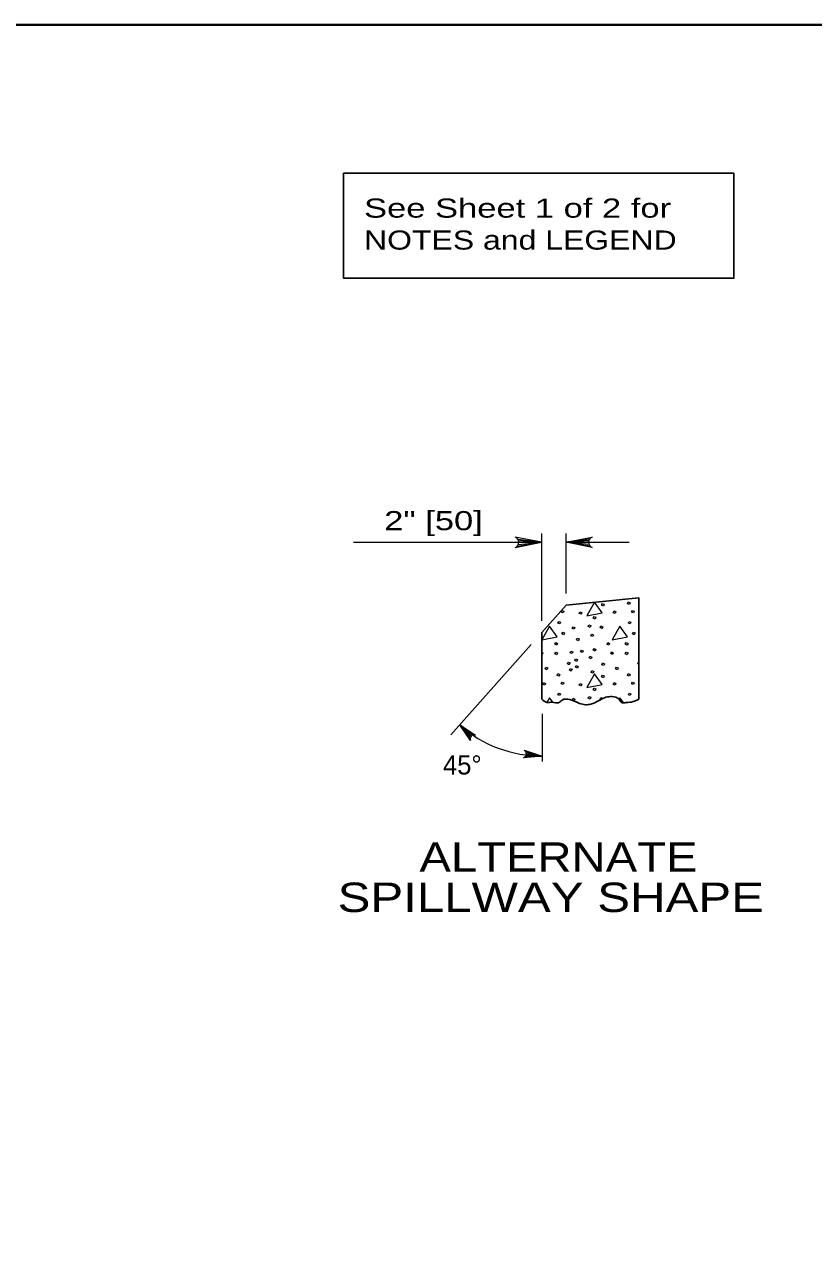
# Model space of a CAD drawing. Extents: x 1083.1 to 1123, y 697.4 to 741.4.
# Drawn here: x 1095.55 to 1101.99, y 708.76 to 718.85 of the extents above; entities that cross this region are included whole.
import ezdxf
from ezdxf.enums import TextEntityAlignment as Align

# ---------------------------------------------------------------- set-up
doc = ezdxf.new("R2010")
doc.units = 0
doc.header["$LTSCALE"] = 0.062
doc.layers.add('1', color=7, linetype='Continuous', lineweight=13)

msp = doc.modelspace()

# ---------------------------------------------------------------- linework, layer by layer
at = {"layer": '1', "lineweight": 25}
for p, q in [((1085.12642, 718.85408), (1116.62642, 718.85408)), ((1099.77208, 713.898), (1099.97033, 714.12092)), ((1099.77208, 713.35442), (1099.77208, 713.898))]:
    msp.add_line(p, q, dxfattribs=at)
at = {"layer": '1'}
for p, q in [((1099.77208, 713.9925), (1099.77208, 714.7035)), ((1099.97033, 714.21542), (1099.97033, 714.7035)), ((1098.23525, 714.63275), (1099.77067, 714.63275)), ((1099.5745, 714.60275), (1099.77067, 714.63275)), ((1099.57675, 714.65983), (1099.77067, 714.63275)), ((1099.58192, 714.61533), (1099.77067, 714.63275)), ((1099.58333, 714.64642), (1099.77067, 714.63275)), ((1099.58533, 714.63275), (1099.77067, 714.63275)), ((1100.16283, 714.65983), (1099.96892, 714.63275)), ((1100.15625, 714.64642), (1099.96892, 714.63275)), ((1100.15775, 714.63275), (1099.96892, 714.63275)), ((1099.96892, 714.63275), (1100.48658, 714.63275)), ((1100.15425, 714.63275), (1099.96892, 714.63275)), ((1100.15767, 714.61533), (1099.96892, 714.63275)), ((1100.16508, 714.60275), (1099.96892, 714.63275)), ((1099.03, 713.0635), (1099.6855, 713.80058)), ((1100.56267, 713.65458), (1100.56425, 713.654)), ((1099.836, 713.36533), (1099.81442, 713.32675)), ((1099.862, 713.32825), (1099.836, 713.36533)), ((1100.41042, 713.36533), (1100.4025, 713.35108)), ((1100.43825, 713.32567), (1100.41042, 713.36533)), ((1099.77675, 713.23475), (1099.77675, 712.84425)), ((1099.19658, 713.05267), (1099.10275, 713.14333)), ((1099.19017, 713.04217), (1099.10275, 713.14333)), ((1099.188, 713.0325), (1099.10275, 713.14333)), ((1099.20467, 713.05867), (1099.10275, 713.14333)), ((1099.2145, 713.06267), (1099.10275, 713.14333)), ((1099.63833, 712.88575), (1099.77658, 712.88933)), ((1099.64142, 712.92575), (1099.77658, 712.88933)), ((1099.644, 712.89467), (1099.77658, 712.88933)), ((1099.64525, 712.91683), (1099.77658, 712.88933)), ((1099.64633, 712.90383), (1099.77658, 712.88933))]:
    msp.add_line(p, q, dxfattribs=at)
at = {"layer": '1', "lineweight": 40}
msp.add_lwpolyline([(1085.12642, 718.85408), (1116.62642, 718.85408), (1116.62642, 697.85408), (1085.12642, 697.85408)], close=True, dxfattribs=at)
at = {"layer": '1', "lineweight": 25}
msp.add_lwpolyline([(1098.15567, 717.64242), (1101.33942, 717.64242), (1101.33942, 716.786), (1098.15567, 716.786)], close=True, dxfattribs=at)
at = {"layer": '1'}
for points in [[(1099.5565, 714.58992), (1099.77067, 714.63275), (1099.5565, 714.67558)], [(1100.18308, 714.58992), (1099.96892, 714.63275), (1100.18308, 714.67558)], [(1100.20183, 714.14342), (1100.14033, 714.0335), (1100.26433, 714.05767), (1100.20392, 714.14375)], [(1099.77208, 713.73667), (1099.7815, 713.73217), (1099.7755, 713.71808), (1099.77208, 713.71967)], [(1100.56425, 713.6375), (1100.55658, 713.6405), (1100.56267, 713.65458)], [(1100.2545, 713.34975), (1100.24817, 713.35225), (1100.25425, 713.36742)], [(1100.25425, 713.36742), (1100.26933, 713.36033), (1100.26733, 713.35567)], [(1099.19042, 713.01708), (1099.10275, 713.14333), (1099.23275, 713.06058)], [(1099.62958, 712.93633), (1099.77658, 712.88933), (1099.62283, 712.87617)]]:
    msp.add_lwpolyline(points, dxfattribs=at)
at = {"layer": '1', "lineweight": 25}
msp.add_lwpolyline([(1099.97033, 714.12092), (1100.56425, 714.17892), (1100.56425, 713.35442)], dxfattribs=at)
at = {"layer": '1'}
for points in [[(1100.26733, 714.13425), (1100.28242, 714.12725), (1100.27542, 714.11317), (1100.26025, 714.11917)], [(1100.478, 714.14642), (1100.49308, 714.14033), (1100.48708, 714.12625), (1100.47192, 714.13225)], [(1099.91058, 713.98717), (1099.92567, 713.98108), (1099.91958, 713.967), (1099.9045, 713.97308)], [(1099.93775, 714.07683), (1099.95292, 714.07083), (1099.94583, 714.05667), (1099.93075, 714.06275)], [(1100.08392, 714.06675), (1100.099, 714.06075), (1100.092, 714.04658), (1100.07683, 714.05267)], [(1100.19883, 714.0275), (1100.21392, 714.02142), (1100.20783, 714.00633), (1100.19275, 714.01333)], [(1100.36208, 714.07283), (1100.37717, 714.06675), (1100.37117, 714.05267), (1100.356, 714.05867)], [(1100.485, 713.98717), (1100.50017, 713.98108), (1100.49408, 713.967), (1100.479, 713.97308)], [(1100.51225, 714.07683), (1100.52733, 714.07083), (1100.52033, 714.05667), (1100.50517, 714.06275)], [(1099.836, 713.94983), (1099.7735, 713.838), (1099.89742, 713.86217)], [(1099.94383, 713.9005), (1099.95892, 713.89342), (1099.95183, 713.87933), (1099.93675, 713.88533)], [(1100.0275, 713.94483), (1100.04258, 713.93775), (1100.0365, 713.92367), (1100.02142, 713.93075)], [(1100.1575, 713.95992), (1100.17258, 713.95392), (1100.16658, 713.93875), (1100.15142, 713.94583)], [(1100.18067, 713.88433), (1100.19575, 713.87833), (1100.18875, 713.86425), (1100.17358, 713.87025)], [(1100.25425, 713.95192), (1100.26933, 713.94483), (1100.26333, 713.93075), (1100.24817, 713.93675)], [(1100.41042, 713.94983), (1100.34792, 713.838), (1100.47192, 713.86217)], [(1100.51825, 713.9005), (1100.53342, 713.89342), (1100.52633, 713.87933), (1100.51125, 713.88533)], [(1099.88633, 713.81483), (1099.9015, 713.80875), (1099.89442, 713.79467), (1099.87933, 713.80075)], [(1100.06175, 713.85108), (1100.07683, 713.84508), (1100.07083, 713.82992), (1100.05567, 713.837)], [(1100.31067, 713.81483), (1100.32575, 713.80775), (1100.31975, 713.79367), (1100.30458, 713.79975)], [(1100.46083, 713.81483), (1100.47592, 713.80875), (1100.46892, 713.79467), (1100.45375, 713.80075)], [(1099.88633, 713.73625), (1099.9015, 713.73017), (1099.89442, 713.71508), (1099.87933, 713.72208)], [(1100.01033, 713.74633), (1100.02542, 713.73925), (1100.01942, 713.72517), (1100.00425, 713.73117)], [(1100.04858, 713.68283), (1100.06375, 713.67575), (1100.05767, 713.66167), (1100.04258, 713.66767)], [(1100.096, 713.75433), (1100.11108, 713.74833), (1100.10408, 713.73317), (1100.08892, 713.74025)], [(1100.1655, 713.704), (1100.18067, 713.69692), (1100.17458, 713.68283), (1100.1595, 713.68983)], [(1100.19883, 713.76642), (1100.21392, 713.75942), (1100.20683, 713.74525), (1100.19175, 713.75233)], [(1100.34092, 713.73925), (1100.356, 713.73217), (1100.35, 713.71808), (1100.33483, 713.72517)], [(1100.46083, 713.73625), (1100.47592, 713.73017), (1100.46892, 713.71508), (1100.45375, 713.72208)], [(1099.80675, 713.61425), (1099.82183, 713.60825), (1099.81483, 713.59308), (1099.79967, 713.60017)], [(1099.98817, 713.65458), (1100.00325, 713.64858), (1099.99725, 713.63442), (1099.98208, 713.6405)], [(1100.00425, 713.60417), (1100.01942, 713.59717), (1100.01333, 713.583), (1099.99825, 713.59008)], [(1100.05367, 713.62742), (1100.06875, 713.62033), (1100.06275, 713.60625), (1100.04758, 713.61325)], [(1100.18167, 713.58608), (1100.19675, 713.58), (1100.19075, 713.56492), (1100.17558, 713.57192)], [(1100.26833, 713.64858), (1100.28342, 713.6415), (1100.27742, 713.62742), (1100.26225, 713.63342)], [(1100.38125, 713.61425), (1100.39633, 713.60825), (1100.38925, 713.59308), (1100.37417, 713.60017)], [(1099.78758, 713.48833), (1099.80267, 713.48225), (1099.79667, 713.46817), (1099.7815, 713.47425)], [(1099.9035, 713.56192), (1099.91858, 713.55583), (1099.91258, 713.54175), (1099.89742, 713.54775)], [(1099.93775, 713.49233), (1099.95292, 713.48633), (1099.94583, 713.47217), (1099.93075, 713.47825)], [(1100.08392, 713.48225), (1100.099, 713.47625), (1100.092, 713.46208), (1100.07683, 713.46817)], [(1100.20283, 713.56092), (1100.14033, 713.449), (1100.26433, 713.47317)], [(1100.26733, 713.54983), (1100.28242, 713.54275), (1100.27542, 713.52858), (1100.26025, 713.53467)], [(1100.36208, 713.48833), (1100.37717, 713.48225), (1100.37117, 713.46817), (1100.356, 713.47425)], [(1100.478, 713.56192), (1100.49308, 713.55583), (1100.48708, 713.54175), (1100.47192, 713.54775)], [(1100.51225, 713.49233), (1100.52733, 713.48633), (1100.52033, 713.47217), (1100.50517, 713.47825)], [(1099.91058, 713.40267), (1099.92567, 713.39658), (1099.91958, 713.3825), (1099.9045, 713.38858)], [(1100.19883, 713.443), (1100.21392, 713.43692), (1100.20783, 713.42183), (1100.19275, 713.42883)], [(1100.485, 713.40267), (1100.50017, 713.39658), (1100.49408, 713.3825), (1100.479, 713.38858)], [(1100.0275, 713.36033), (1100.04258, 713.35325), (1100.0365, 713.33917), (1100.02142, 713.34625)], [(1100.1575, 713.37542), (1100.17258, 713.36942), (1100.16658, 713.35425), (1100.15142, 713.36133)]]:
    msp.add_lwpolyline(points, close=True, dxfattribs=at)
for centre, radius, start, end in [((1099.53919, 714.63277), 0.04623, 292.08605, 67.91218), ((1100.20037, 714.63277), 0.04623, 112.08782, 247.91395), ((1099.77207, 713.89797), 1.00868, 228.42766, 270.25414)]:
    msp.add_arc(centre, radius, start, end, dxfattribs=at)
for centre, start_param, end_param in [((1099.22043, 713.03021), 1.18969161, 3.56030475), ((1099.61407, 712.90765), 4.98530398, 7.35591712)]:
    msp.add_ellipse(centre, major_axis=(0.03263, 0), ratio=0.999895, start_param=start_param, end_param=end_param, dxfattribs=at)
at = {"layer": '1', "lineweight": 25}
msp.add_spline([(1100.56425, 713.35442), (1100.5185, 713.33333), (1100.4585, 713.32525), (1100.42375, 713.326), (1100.39917, 713.355), (1100.34683, 713.37425), (1100.29525, 713.36867), (1100.24683, 713.34608), (1100.19742, 713.32225), (1100.16242, 713.31125), (1100.11808, 713.30942), (1100.06917, 713.32333), (1100.00025, 713.35067), (1099.93908, 713.34658), (1099.90875, 713.32492), (1099.85733, 713.32858), (1099.81417, 713.32675), (1099.77208, 713.35442)], degree=3, dxfattribs=at)

# ---------------------------------------------------------------- texts
at = {"layer": '1'}
for s, height, width, p in [('See Sheet 1 of 2 for ', 0.156, 1.35, (1098.32233, 717.28075)), ('NOTES and LEGEND', 0.156, 1.25, (1098.32233, 717.02008)), ('ALTERNATE', 0.24, 1.2, (1098.77433, 711.946)), ('SPILLWAY SHAPE', 0.24, 1.25, (1098.10675, 711.6175))]:
    msp.add_text(s, height=height, dxfattribs=dict(at, width=width)).set_placement(p)
at = {"layer": '1', "width": 1.35}
msp.add_text('2" [50]', height=0.156, dxfattribs=at).set_placement((1098.88912, 714.73142), align=Align.CENTER)
at = {"layer": '1'}
msp.add_text('45°', height=0.156, dxfattribs=at).set_placement((1099.12413, 712.73908), align=Align.CENTER)

doc.saveas('drawing.dxf')
